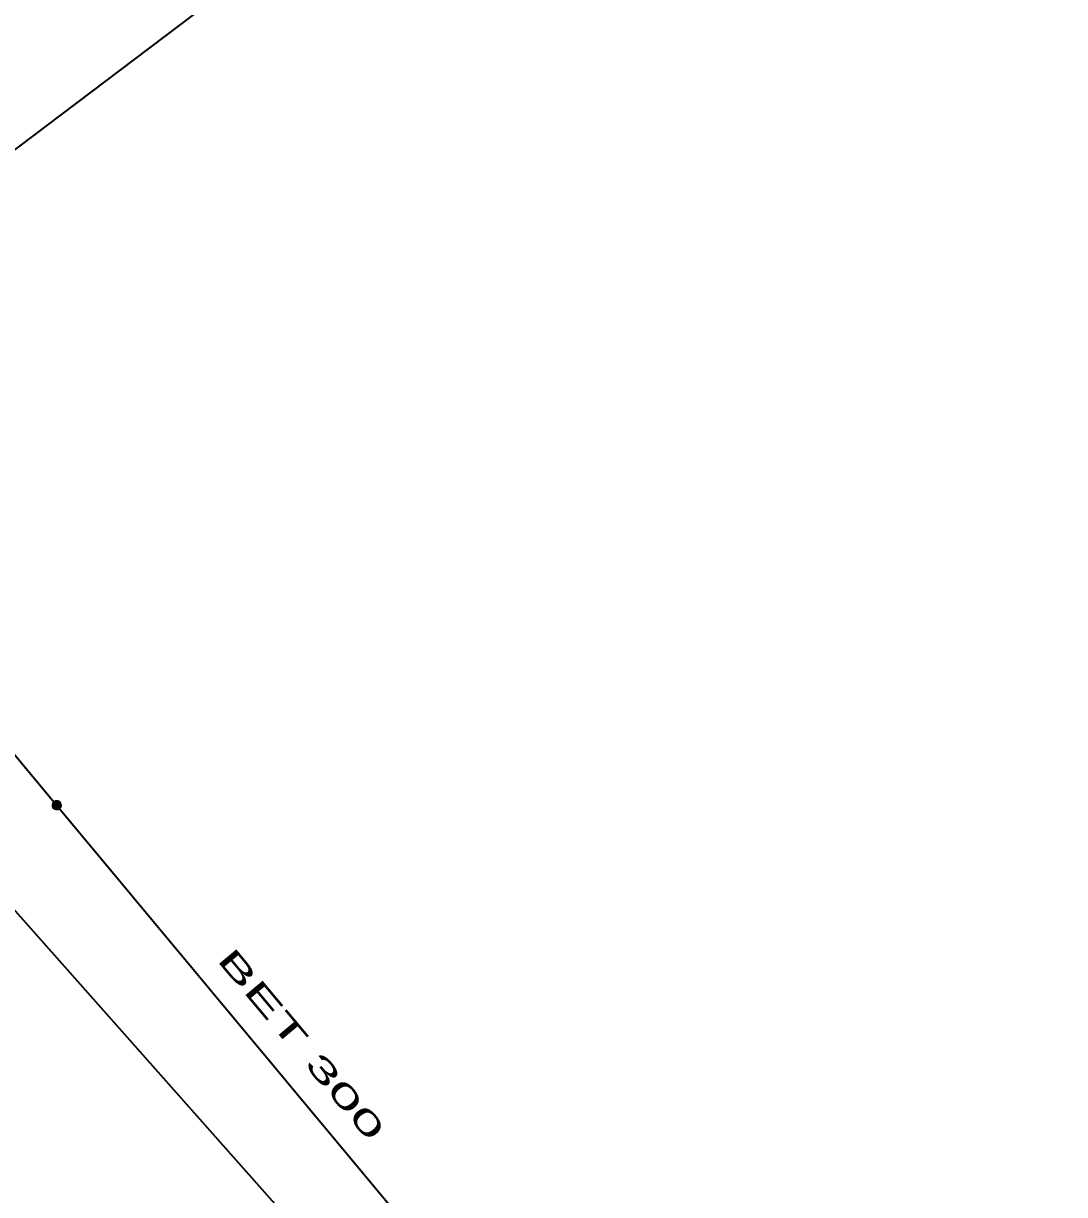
# Model space of a CAD drawing. Extents: x -873619 to -867639, y -1015082 to -1012326.
# Drawn here: x -867956.1 to -867904.9, y -1012758.3 to -1012700.7 of the extents above; entities that cross this region are included whole.
import ezdxf

# ---------------------------------------------------------------- set-up
doc = ezdxf.new("R2010")
doc.units = 0
doc.header["$LTSCALE"] = 0.44
for name, color, linetype, lineweight in [('1', 7, 'Continuous', 13), ('21', 7, 'Continuous', 35), ('32', 7, 'Continuous', 13)]:
    doc.layers.add(name, color=color, linetype=linetype, lineweight=lineweight)

msp = doc.modelspace()

# ---------------------------------------------------------------- linework, layer by layer
at = {"layer": '1', "lineweight": 35}
for points in [[(-867928.158, -1012682.175), (-867928.532, -1012682.575), (-867928.834, -1012682.846), (-867929.235, -1012683.248), (-867941.259, -1012695.377), (-867959.972, -1012709.533), (-867967.543, -1012714.627), (-867970.064, -1012716.534), (-867974.611, -1012725.697)], [(-867974.611, -1012725.697), (-867974.301, -1012725.775), (-867973.868, -1012725.89), (-867972.988, -1012726.12), (-867972.44, -1012726.34), (-867942.73, -1012759.87), (-867932.66, -1012771.332), (-867928.969, -1012774.977), (-867916.529, -1012789.697), (-867904.95, -1012804.27)]]:
    msp.add_lwpolyline(points, dxfattribs=at)
at = {"layer": '21'}
for points in [[(-867981.801, -1012701.313), (-867966.749, -1012724.362), (-867954.427, -1012739.171)], [(-867954.427, -1012739.171), (-867935.69, -1012761.69), (-867931.98, -1012769.6), (-867931.383, -1012770.263)]]:
    msp.add_lwpolyline(points, dxfattribs=at)
at = {"layer": '32'}
for points in [[(-867954.225, -1012739.136), (-867954.231, -1012739.084), (-867954.248, -1012739.034), (-867954.277, -1012738.99), (-867954.314, -1012738.953), (-867954.359, -1012738.926), (-867954.409, -1012738.909), (-867954.462, -1012738.905), (-867954.514, -1012738.912), (-867954.563, -1012738.931), (-867954.606, -1012738.96), (-867954.642, -1012738.999), (-867954.668, -1012739.044), (-867954.684, -1012739.095), (-867954.687, -1012739.147), (-867954.679, -1012739.199), (-867954.659, -1012739.248), (-867954.628, -1012739.291), (-867954.589, -1012739.325), (-867954.543, -1012739.351), (-867954.492, -1012739.365), (-867954.439, -1012739.367), (-867954.388, -1012739.357), (-867954.34, -1012739.336), (-867954.297, -1012739.305), (-867954.263, -1012739.264), (-867954.239, -1012739.218), (-867954.227, -1012739.167)], [(-867954.255, -1012739.136), (-867954.261, -1012739.087), (-867954.278, -1012739.041), (-867954.306, -1012739.001), (-867954.343, -1012738.969), (-867954.387, -1012738.947), (-867954.435, -1012738.936), (-867954.484, -1012738.936), (-867954.531, -1012738.949), (-867954.574, -1012738.973), (-867954.61, -1012739.006), (-867954.637, -1012739.047), (-867954.653, -1012739.094), (-867954.657, -1012739.143), (-867954.65, -1012739.191), (-867954.631, -1012739.236), (-867954.601, -1012739.276), (-867954.563, -1012739.307), (-867954.519, -1012739.327), (-867954.471, -1012739.337), (-867954.422, -1012739.335), (-867954.375, -1012739.32), (-867954.332, -1012739.295), (-867954.298, -1012739.261), (-867954.272, -1012739.219), (-867954.258, -1012739.172)], [(-867954.285, -1012739.136), (-867954.291, -1012739.091), (-867954.308, -1012739.049), (-867954.336, -1012739.014), (-867954.372, -1012738.987), (-867954.414, -1012738.97), (-867954.459, -1012738.965), (-867954.504, -1012738.971), (-867954.545, -1012738.99), (-867954.58, -1012739.018), (-867954.607, -1012739.055), (-867954.623, -1012739.097), (-867954.627, -1012739.142), (-867954.62, -1012739.187), (-867954.601, -1012739.228), (-867954.572, -1012739.262), (-867954.535, -1012739.288), (-867954.492, -1012739.304), (-867954.447, -1012739.307), (-867954.402, -1012739.299), (-867954.362, -1012739.279), (-867954.328, -1012739.25), (-867954.302, -1012739.212), (-867954.288, -1012739.169)], [(-867954.315, -1012739.136), (-867954.32, -1012739.095), (-867954.338, -1012739.058), (-867954.365, -1012739.027), (-867954.4, -1012739.006), (-867954.44, -1012738.995), (-867954.481, -1012738.997), (-867954.52, -1012739.01), (-867954.554, -1012739.034), (-867954.579, -1012739.066), (-867954.594, -1012739.104), (-867954.597, -1012739.145), (-867954.589, -1012739.185), (-867954.569, -1012739.221), (-867954.54, -1012739.25), (-867954.503, -1012739.269), (-867954.463, -1012739.277), (-867954.422, -1012739.273), (-867954.384, -1012739.258), (-867954.352, -1012739.232), (-867954.329, -1012739.198), (-867954.316, -1012739.159)], [(-867954.345, -1012739.136), (-867954.35, -1012739.1), (-867954.368, -1012739.068), (-867954.394, -1012739.043), (-867954.428, -1012739.028), (-867954.464, -1012739.025), (-867954.499, -1012739.033), (-867954.53, -1012739.053), (-867954.553, -1012739.081), (-867954.566, -1012739.115), (-867954.566, -1012739.152), (-867954.555, -1012739.187), (-867954.534, -1012739.216), (-867954.504, -1012739.237), (-867954.469, -1012739.247), (-867954.432, -1012739.245), (-867954.398, -1012739.231), (-867954.371, -1012739.208), (-867954.352, -1012739.176), (-867954.345, -1012739.141)], [(-867954.375, -1012739.136), (-867954.38, -1012739.105), (-867954.397, -1012739.079), (-867954.423, -1012739.062), (-867954.453, -1012739.055), (-867954.484, -1012739.059), (-867954.511, -1012739.076), (-867954.529, -1012739.1), (-867954.537, -1012739.131), (-867954.533, -1012739.161), (-867954.518, -1012739.189), (-867954.494, -1012739.208), (-867954.464, -1012739.217), (-867954.433, -1012739.214), (-867954.405, -1012739.2), (-867954.385, -1012739.176), (-867954.375, -1012739.147)], [(-867954.405, -1012739.136), (-867954.41, -1012739.112), (-867954.427, -1012739.094), (-867954.45, -1012739.085), (-867954.474, -1012739.088), (-867954.495, -1012739.102), (-867954.506, -1012739.124), (-867954.506, -1012739.149), (-867954.494, -1012739.17), (-867954.474, -1012739.184), (-867954.449, -1012739.187), (-867954.426, -1012739.178), (-867954.41, -1012739.16)], [(-867954.435, -1012739.136), (-867954.44, -1012739.121), (-867954.455, -1012739.115), (-867954.47, -1012739.119), (-867954.477, -1012739.133), (-867954.473, -1012739.148), (-867954.46, -1012739.157), (-867954.445, -1012739.154), (-867954.435, -1012739.142)]]:
    msp.add_lwpolyline(points, close=True, dxfattribs=at)

# ---------------------------------------------------------------- texts
at = {"layer": '1', "width": 2.05}
msp.add_text('BET 300 ', height=1.1, rotation=310, dxfattribs=at).set_placement((-867946.636, -1012746.735))

doc.saveas('drawing.dxf')
